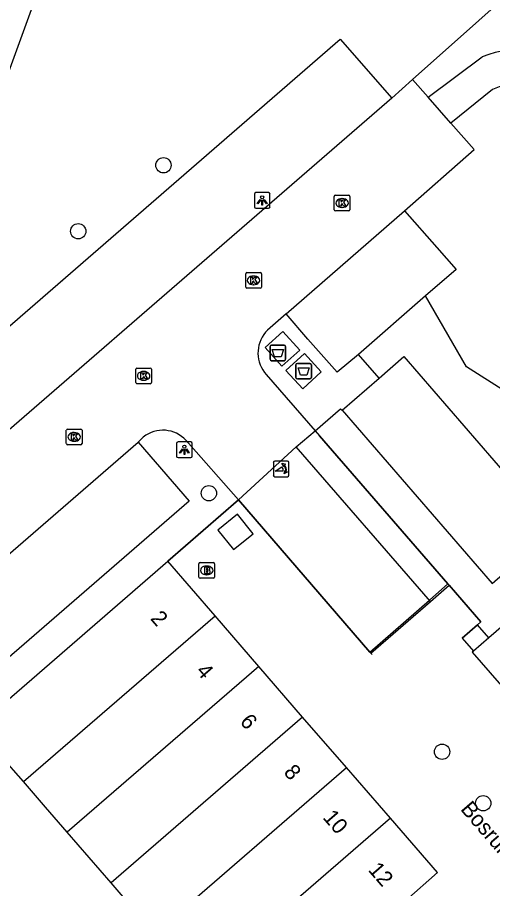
# Model space of a CAD drawing. Extents: x 156664 to 157568, y 383571 to 384421.
# Drawn here: x 156895.5 to 156925.9, y 384254.3 to 384310 of the extents above; entities that cross this region are included whole.
import ezdxf

# ---------------------------------------------------------------- set-up
doc = ezdxf.new("R2010")
doc.units = 0
for name, color, linetype in [('IMGEO_Afval_apart_plaats', 7, 'Continuous'), ('IMGEO_Berm_open', 7, 'Continuous'), ('IMGEO_Boom', 7, 'Continuous'), ('IMGEO_Brandkraan', 7, 'Continuous'), ('IMGEO_Kolk', 7, 'Continuous'), ('IMGEO_Lichtpunt', 7, 'Continuous'), ('IMGEO_Lijnafwatering', 7, 'Continuous'), ('IMGEO_Loofbos', 7, 'Continuous'), ('IMGEO_Muur', 7, 'Continuous'), ('IMGEO_Openbare_ruimte_label', 7, 'Continuous'), ('IMGEO_Pand', 7, 'Continuous'), ('IMGEO_Pand_nummerreeks', 7, 'Continuous'), ('IMGEO_Parkeervlak_open', 7, 'Continuous'), ('IMGEO_Poller', 7, 'Continuous'), ('IMGEO_Rijbaan_lokaal_open', 7, 'Continuous'), ('IMGEO_Voetpad_gesloten', 7, 'Continuous'), ('IMGEO_Voetpad_halfverhard', 7, 'Continuous'), ('IMGEO_Voetpad_open', 7, 'Continuous')]:
    doc.layers.add(name, color=color, linetype=linetype)

msp = doc.modelspace()

# ---------------------------------------------------------------- linework, layer by layer
at = {"layer": 'IMGEO_Afval_apart_plaats'}
for p, q in [((156911.678, 384288.16), (156911.678, 384288.96)), ((156911.678, 384288.96), (156911.678, 384288.16)), ((156911.778, 384289.06), (156912.568, 384289.06)), ((156912.568, 384289.06), (156911.778, 384289.06)), ((156912.668, 384288.96), (156912.668, 384288.16)), ((156912.668, 384288.16), (156912.668, 384288.96)), ((156912.568, 384288.06), (156911.778, 384288.06)), ((156911.778, 384288.06), (156912.568, 384288.06)), ((156913.424, 384287.89), (156914.214, 384287.89)), ((156914.214, 384287.89), (156913.424, 384287.89)), ((156913.324, 384286.99), (156913.324, 384287.79)), ((156913.324, 384287.79), (156913.324, 384286.99)), ((156914.314, 384287.79), (156914.314, 384286.99)), ((156914.314, 384286.99), (156914.314, 384287.79)), ((156914.214, 384286.89), (156913.424, 384286.89)), ((156913.424, 384286.89), (156914.214, 384286.89))]:
    msp.add_line(p, q, dxfattribs=at)
for points in [[(156911.821, 384288.774), (156912.525, 384288.774), (156912.376, 384288.304), (156911.97, 384288.304), (156911.821, 384288.774)], [(156913.467, 384287.604), (156914.171, 384287.604), (156914.022, 384287.134), (156913.616, 384287.134), (156913.467, 384287.604)]]:
    msp.add_lwpolyline(points, dxfattribs=at)
for centre, start, end in [((156911.778, 384288.96), 90, 180), ((156911.778, 384288.96), 90, 180), ((156912.568, 384288.96), 0, 90), ((156912.568, 384288.96), 360, 90), ((156911.778, 384288.16), 180, 270), ((156911.778, 384288.16), 180, 270), ((156912.568, 384288.16), 270, 0), ((156912.568, 384288.16), 270, 0), ((156913.424, 384287.79), 90, 180), ((156913.424, 384287.79), 90, 180), ((156914.214, 384287.79), 0, 90), ((156914.214, 384287.79), 360, 90), ((156913.424, 384286.99), 180, 270), ((156913.424, 384286.99), 180, 270), ((156914.214, 384286.99), 270, 0), ((156914.214, 384286.99), 270, 0)]:
    msp.add_arc(centre, 0.1, start, end, dxfattribs=at)
at = {"layer": 'IMGEO_Berm_open'}
msp.add_lwpolyline([(156918.639, 384286.952), (156917.316, 384288.456)], dxfattribs=at)
at = {"layer": 'IMGEO_Boom'}
for centre in [(156904.869, 384300.549), (156899.424, 384296.331), (156907.767, 384279.588), (156922.662, 384263.067), (156925.29, 384259.773)]:
    msp.add_circle(centre, 0.489, dxfattribs=at)
at = {"layer": 'IMGEO_Brandkraan'}
for p, q in [((156907.134, 384274.229), (156907.134, 384275.081)), ((156907.209, 384275.155), (156908.061, 384275.155)), ((156908.135, 384275.081), (156908.135, 384274.229)), ((156907.622, 384274.935), (156907.647, 384274.935)), ((156908.061, 384274.155), (156907.209, 384274.155)), ((156907.645, 384274.375), (156907.62, 384274.375))]:
    msp.add_line(p, q, dxfattribs=at)
for points in [[(156907.134, 384274.229), (156907.134, 384275.081)], [(156907.209, 384275.155), (156908.061, 384275.155)], [(156908.135, 384275.081), (156908.135, 384274.229)], [(156907.482, 384274.855), (156907.482, 384274.455), (156907.695, 384274.455)], [(156907.713, 384274.855), (156907.482, 384274.855)], [(156907.661, 384274.774), (156907.607, 384274.774), (156907.607, 384274.698)], [(156907.607, 384274.698), (156907.66, 384274.698)], [(156907.669, 384274.622), (156907.607, 384274.622), (156907.607, 384274.541)], [(156907.607, 384274.541), (156907.669, 384274.541)], [(156908.061, 384274.155), (156907.209, 384274.155)]]:
    msp.add_lwpolyline(points, dxfattribs=at)
for centre, radius, start, end in [((156907.211, 384275.079), 0.0765, 91.552, 178.448), ((156907.211, 384275.079), 0.0765, 91.552, 178.448), ((156908.059, 384275.079), 0.0765, 1.552, 88.448), ((156908.059, 384275.079), 0.0765, 1.552, 88.448), ((156907.662, 384274.736), 0.0379, 267.8285, 90.9355), ((156907.67, 384274.581), 0.0404, 269.8759, 90.5077), ((156907.701, 384274.706), 0.251, 268.6676, 293.5347), ((156907.717, 384274.71), 0.145, 59.4692, 91.5367), ((156907.742, 384274.757), 0.0922, 285.5137, 58.1501), ((156907.747, 384274.565), 0.105, 301.3115, 78.989), ((156907.211, 384274.231), 0.0765, 181.552, 268.448), ((156907.211, 384274.231), 0.0765, 181.552, 268.448), ((156908.059, 384274.231), 0.0765, 271.552, 358.448), ((156908.059, 384274.231), 0.0765, 271.552, 358.448)]:
    msp.add_arc(centre, radius, start, end, dxfattribs=at)
for centre, major_axis, ratio, start_param, end_param in [((156907.621, 384274.655), (-0.387, 0.002), 0.722429, 4.712389, 7.853982), ((156907.646, 384274.655), (-0.39, 0.002), 0.717154, 1.570796, 4.712389)]:
    msp.add_ellipse(centre, major_axis=major_axis, ratio=ratio, start_param=start_param, end_param=end_param, dxfattribs=at)
at = {"layer": 'IMGEO_Kolk'}
for p, q in [((156915.779, 384297.71), (156915.779, 384298.562)), ((156915.854, 384298.636), (156916.706, 384298.636)), ((156916.267, 384298.416), (156916.292, 384298.416)), ((156916.78, 384298.562), (156916.78, 384297.71)), ((156916.29, 384297.856), (156916.265, 384297.856)), ((156916.706, 384297.636), (156915.854, 384297.636)), ((156910.12, 384292.767), (156910.12, 384293.619)), ((156910.195, 384293.693), (156911.047, 384293.693)), ((156910.608, 384293.473), (156910.633, 384293.473)), ((156911.121, 384293.619), (156911.121, 384292.767)), ((156910.631, 384292.913), (156910.606, 384292.913)), ((156911.047, 384292.693), (156910.195, 384292.693)), ((156903.101, 384286.665), (156903.101, 384287.517)), ((156903.176, 384287.591), (156904.028, 384287.591)), ((156903.589, 384287.371), (156903.614, 384287.371)), ((156904.102, 384287.517), (156904.102, 384286.665)), ((156903.612, 384286.811), (156903.587, 384286.811)), ((156904.028, 384286.591), (156903.176, 384286.591)), ((156898.665, 384282.764), (156898.665, 384283.616)), ((156898.74, 384283.69), (156899.592, 384283.69)), ((156899.153, 384283.47), (156899.178, 384283.47)), ((156899.666, 384283.616), (156899.666, 384282.764)), ((156899.176, 384282.91), (156899.151, 384282.91)), ((156899.592, 384282.69), (156898.74, 384282.69))]:
    msp.add_line(p, q, dxfattribs=at)
for points in [[(156915.779, 384297.71), (156915.779, 384298.562)], [(156915.854, 384298.636), (156916.706, 384298.636)], [(156916.78, 384298.562), (156916.78, 384297.71)], [(156916.1, 384298.336), (156916.223, 384298.336), (156916.223, 384298.185), (156916.353, 384298.336), (156916.517, 384298.336), (156916.371, 384298.185), (156916.524, 384297.936), (156916.372, 384297.936), (156916.287, 384298.1), (156916.223, 384298.033), (156916.223, 384297.936), (156916.1, 384297.936), (156916.1, 384298.336)], [(156916.706, 384297.636), (156915.854, 384297.636)], [(156910.12, 384292.767), (156910.12, 384293.619)], [(156910.195, 384293.693), (156911.047, 384293.693)], [(156910.441, 384293.393), (156910.564, 384293.393), (156910.564, 384293.242), (156910.694, 384293.393), (156910.858, 384293.393), (156910.712, 384293.242), (156910.865, 384292.993), (156910.713, 384292.993), (156910.628, 384293.157), (156910.564, 384293.09), (156910.564, 384292.993), (156910.441, 384292.993), (156910.441, 384293.393)], [(156911.121, 384293.619), (156911.121, 384292.767)], [(156911.047, 384292.693), (156910.195, 384292.693)], [(156903.101, 384286.665), (156903.101, 384287.517)], [(156903.176, 384287.591), (156904.028, 384287.591)], [(156903.422, 384287.291), (156903.545, 384287.291), (156903.545, 384287.14), (156903.675, 384287.291), (156903.839, 384287.291), (156903.693, 384287.14), (156903.846, 384286.891), (156903.694, 384286.891), (156903.609, 384287.055), (156903.545, 384286.988), (156903.545, 384286.891), (156903.422, 384286.891), (156903.422, 384287.291)], [(156904.102, 384287.517), (156904.102, 384286.665)], [(156904.028, 384286.591), (156903.176, 384286.591)], [(156898.665, 384282.764), (156898.665, 384283.616)], [(156898.74, 384283.69), (156899.592, 384283.69)], [(156898.986, 384283.39), (156899.109, 384283.39), (156899.109, 384283.239), (156899.239, 384283.39), (156899.403, 384283.39), (156899.257, 384283.239), (156899.41, 384282.99), (156899.258, 384282.99), (156899.173, 384283.154), (156899.109, 384283.087), (156899.109, 384282.99), (156898.986, 384282.99), (156898.986, 384283.39)], [(156899.666, 384283.616), (156899.666, 384282.764)], [(156899.592, 384282.69), (156898.74, 384282.69)]]:
    msp.add_lwpolyline(points, dxfattribs=at)
for centre, start, end in [((156915.856, 384298.56), 91.552, 178.448), ((156915.856, 384298.56), 91.552, 178.448), ((156916.704, 384298.56), 1.552, 88.448), ((156916.704, 384298.56), 1.552, 88.448), ((156915.856, 384297.712), 181.552, 268.448), ((156915.856, 384297.712), 181.552, 268.448), ((156916.704, 384297.712), 271.552, 358.448), ((156916.704, 384297.712), 271.552, 358.448), ((156910.197, 384293.617), 91.552, 178.448), ((156910.197, 384293.617), 91.552, 178.448), ((156911.045, 384293.617), 1.552, 88.448), ((156911.045, 384293.617), 1.552, 88.448), ((156910.197, 384292.769), 181.552, 268.448), ((156910.197, 384292.769), 181.552, 268.448), ((156911.045, 384292.769), 271.552, 358.448), ((156911.045, 384292.769), 271.552, 358.448), ((156903.178, 384287.515), 91.552, 178.448), ((156903.178, 384287.515), 91.552, 178.448), ((156904.026, 384287.515), 1.552, 88.448), ((156904.026, 384287.515), 1.552, 88.448), ((156903.178, 384286.667), 181.552, 268.448), ((156903.178, 384286.667), 181.552, 268.448), ((156904.026, 384286.667), 271.552, 358.448), ((156904.026, 384286.667), 271.552, 358.448), ((156898.742, 384283.614), 91.552, 178.448), ((156898.742, 384283.614), 91.552, 178.448), ((156899.59, 384283.614), 1.552, 88.448), ((156899.59, 384283.614), 1.552, 88.448), ((156898.742, 384282.766), 181.552, 268.448), ((156898.742, 384282.766), 181.552, 268.448), ((156899.59, 384282.766), 271.552, 358.448), ((156899.59, 384282.766), 271.552, 358.448)]:
    msp.add_arc(centre, 0.0765, start, end, dxfattribs=at)
for centre, major_axis, ratio, start_param, end_param in [((156916.266, 384298.136), (-0.387, 0.002), 0.722429, 4.712389, 7.853982), ((156916.291, 384298.136), (-0.39, 0.002), 0.717154, 1.570796, 4.712389), ((156910.607, 384293.193), (-0.387, 0.002), 0.722429, 4.712389, 7.853982), ((156910.632, 384293.193), (-0.39, 0.002), 0.717154, 1.570796, 4.712389), ((156903.588, 384287.091), (-0.387, 0.002), 0.722429, 4.712389, 7.853982), ((156903.613, 384287.091), (-0.39, 0.002), 0.717154, 1.570796, 4.712389), ((156899.152, 384283.19), (-0.387, 0.002), 0.722429, 4.712389, 7.853982), ((156899.177, 384283.19), (-0.39, 0.002), 0.717154, 1.570796, 4.712389)]:
    msp.add_ellipse(centre, major_axis=major_axis, ratio=ratio, start_param=start_param, end_param=end_param, dxfattribs=at)
at = {"layer": 'IMGEO_Lichtpunt'}
for p, q in [((156910.677, 384298.708), (156910.677, 384297.901)), ((156910.677, 384298.708), (156910.677, 384297.901)), ((156911.579, 384298.803), (156910.771, 384298.803)), ((156911.579, 384298.803), (156910.771, 384298.803)), ((156911.673, 384297.901), (156911.673, 384298.708)), ((156911.673, 384297.901), (156911.673, 384298.708)), ((156910.771, 384297.807), (156911.579, 384297.807)), ((156910.771, 384297.807), (156911.579, 384297.807)), ((156906.608, 384282.865), (156905.8, 384282.865)), ((156906.608, 384282.865), (156905.8, 384282.865)), ((156905.706, 384282.77), (156905.706, 384281.963)), ((156905.706, 384282.77), (156905.706, 384281.963)), ((156906.702, 384281.963), (156906.702, 384282.77)), ((156906.702, 384281.963), (156906.702, 384282.77)), ((156905.8, 384281.869), (156906.608, 384281.869)), ((156905.8, 384281.869), (156906.608, 384281.869))]:
    msp.add_line(p, q, dxfattribs=at)
for points in [[(156911.051, 384298.372), (156911.09, 384298.344), (156910.902, 384298.082), (156910.864, 384298.109), (156911.051, 384298.372)], [(156911.153, 384298.324), (156911.2, 384298.324), (156911.2, 384298.002), (156911.153, 384298.002), (156911.153, 384298.324)], [(156911.263, 384298.344), (156911.301, 384298.371), (156911.488, 384298.109), (156911.449, 384298.081), (156911.263, 384298.344)], [(156906.08, 384282.434), (156906.119, 384282.406), (156905.931, 384282.144), (156905.893, 384282.171), (156906.08, 384282.434)], [(156906.182, 384282.386), (156906.229, 384282.386), (156906.229, 384282.064), (156906.182, 384282.064), (156906.182, 384282.386)], [(156906.292, 384282.406), (156906.33, 384282.433), (156906.517, 384282.171), (156906.478, 384282.143), (156906.292, 384282.406)]]:
    msp.add_lwpolyline(points, dxfattribs=at)
for centre in [(156911.176, 384298.506), (156906.205, 384282.568)]:
    msp.add_circle(centre, 0.0994, dxfattribs=at)
for centre, start, end in [((156910.771, 384298.708), 90, 180), ((156910.771, 384298.708), 90, 180), ((156911.579, 384298.708), 0, 90), ((156911.579, 384298.708), 0, 90), ((156910.771, 384297.901), 180, 270), ((156910.771, 384297.901), 180, 270), ((156911.579, 384297.901), 270, 0), ((156911.579, 384297.901), 270, 360), ((156905.8, 384282.77), 90, 180), ((156905.8, 384282.77), 90, 180), ((156906.608, 384282.77), 0, 90), ((156906.608, 384282.77), 0, 90), ((156905.8, 384281.963), 180, 270), ((156905.8, 384281.963), 180, 270), ((156906.608, 384281.963), 270, 0), ((156906.608, 384281.963), 270, 360)]:
    msp.add_arc(centre, 0.0946, start, end, dxfattribs=at)
at = {"layer": 'IMGEO_Lijnafwatering'}
msp.add_lwpolyline([(156918.044, 384269.439), (156921.85, 384272.758), (156923.04, 384273.795)], dxfattribs=at)
at = {"layer": 'IMGEO_Loofbos'}
for points in [[(156920.779, 384306.033), (156933.486, 384317.366)], [(156946.464, 384285.343), (156940.187, 384279.465), (156934.032, 384281.434), (156924.213, 384287.669), (156921.611, 384292.197)]]:
    msp.add_lwpolyline(points, dxfattribs=at)
at = {"layer": 'IMGEO_Muur'}
for points in [[(156923.04, 384273.795), (156914.83, 384283.252)], [(156909.656, 384279.17), (156905.142, 384275.238)], [(156918.044, 384269.439), (156909.656, 384279.17)], [(156923.11, 384273.714), (156923.04, 384273.795)], [(156924.923, 384271.172), (156925.147, 384271.369), (156923.11, 384273.714)], [(156923.948, 384270.32), (156924.923, 384271.172)], [(156918.114, 384269.357), (156918.044, 384269.439)], [(156918.189, 384269.271), (156918.114, 384269.357)]]:
    msp.add_lwpolyline(points, dxfattribs=at)
at = {"layer": 'IMGEO_Pand'}
for points in [[(156902.064, 384326.017), (156889.74, 384292.159), (156855.895, 384304.479), (156868.199, 384338.324), (156902.064, 384326.017)], [(156895.921, 384261.156), (156894.513, 384262.782), (156892.903, 384264.64), (156905.142, 384275.238)], [(156908.162, 384271.749), (156905.142, 384275.238)], [(156931.448, 384275.362), (156925.642, 384270.338)], [(156895.921, 384261.156), (156908.162, 384271.749)], [(156910.96, 384268.517), (156908.162, 384271.749)], [(156925.642, 384270.338), (156924.671, 384269.498)], [(156924.671, 384269.498), (156924.595, 384269.432), (156927.603, 384265.957)], [(156910.96, 384268.517), (156898.723, 384257.922)], [(156913.757, 384265.285), (156910.96, 384268.517)], [(156913.757, 384265.285), (156901.526, 384254.688)], [(156916.555, 384262.053), (156913.757, 384265.285)], [(156904.328, 384251.453), (156916.555, 384262.053)], [(156919.359, 384258.813), (156916.555, 384262.053)], [(156898.723, 384257.922), (156897.327, 384259.534), (156895.921, 384261.156)], [(156919.359, 384258.813), (156907.137, 384248.212)], [(156920.35, 384253.561), (156922.366, 384255.339), (156919.359, 384258.813)], [(156901.526, 384254.688), (156900.121, 384256.309), (156898.723, 384257.922)], [(156904.328, 384251.453), (156902.944, 384253.05), (156901.526, 384254.688)]]:
    msp.add_lwpolyline(points, dxfattribs=at)
at = {"layer": 'IMGEO_Parkeervlak_open'}
for points in [[(156881.088, 384277.119), (156880.566, 384277.726), (156916.164, 384308.614), (156919.449, 384304.847)], [(156920.266, 384297.637), (156922.327, 384295.29), (156923.556, 384293.891), (156921.611, 384292.197)], [(156921.611, 384292.197), (156917.316, 384288.456)], [(156917.316, 384288.456), (156915.965, 384287.32), (156914.093, 384289.439), (156912.712, 384291.056)], [(156903.248, 384282.862), (156906.505, 384279.09), (156884.305, 384259.85), (156881.05, 384263.616)]]:
    msp.add_lwpolyline(points, dxfattribs=at)
at = {"layer": 'IMGEO_Poller'}
for p, q in [((156911.886, 384281.546), (156911.886, 384280.739)), ((156911.886, 384281.546), (156911.886, 384280.739)), ((156912.788, 384281.641), (156911.98, 384281.641)), ((156912.788, 384281.641), (156911.98, 384281.641)), ((156912.882, 384280.739), (156912.882, 384281.546)), ((156912.882, 384280.739), (156912.882, 384281.546)), ((156911.98, 384280.644), (156912.788, 384280.644)), ((156911.98, 384280.644), (156912.788, 384280.644))]:
    msp.add_line(p, q, dxfattribs=at)
for points in [[(156912.521, 384280.997), (156912.008, 384280.997), (156912.438, 384281.272)], [(156912.565, 384281.37), (156912.553, 384281.297), (156912.428, 384281.502)], [(156912.428, 384281.502), (156912.659, 384281.436), (156912.588, 384281.404)], [(156912.581, 384280.825), (156912.647, 384281.056), (156912.677, 384280.988)], [(156912.713, 384280.961), (156912.785, 384280.95), (156912.581, 384280.825)]]:
    msp.add_lwpolyline(points, dxfattribs=at)
for centre, radius, start, end in [((156911.98, 384281.546), 0.0946, 90, 180), ((156911.98, 384281.546), 0.0946, 90, 180), ((156912.193, 384281.047), 0.332, 351.3247, 42.4854), ((156912.207, 384281.057), 0.476, 351.7527, 41.1691), ((156912.207, 384281.057), 0.516, 349.3569, 42.2912), ((156912.788, 384281.546), 0.0946, 0, 90), ((156912.788, 384281.546), 0.0946, 0, 90), ((156911.98, 384280.739), 0.0946, 180, 270), ((156911.98, 384280.739), 0.0946, 180, 270), ((156912.788, 384280.739), 0.0946, 270, 0), ((156912.788, 384280.739), 0.0946, 270, 0)]:
    msp.add_arc(centre, radius, start, end, dxfattribs=at)
at = {"layer": 'IMGEO_Rijbaan_lokaal_open'}
for points in [[(156919.449, 384304.847), (156920.779, 384306.033)], [(156921.768, 384304.903), (156920.779, 384306.033)], [(156919.449, 384304.847), (156883.807, 384273.954)], [(156923.23, 384303.234), (156921.768, 384304.903)], [(156920.266, 384297.637), (156924.705, 384301.55), (156923.23, 384303.234)], [(156912.712, 384291.056), (156920.266, 384297.637)], [(156912.712, 384291.056), (156911.517, 384290.014)], [(156911.321, 384287.31), (156911.436, 384287.174), (156914.55, 384283.577)], [(156913.341, 384282.548), (156914.55, 384283.577)], [(156881.05, 384263.616), (156903.248, 384282.862)], [(156903.581, 384283.18), (156903.248, 384282.862)], [(156909.656, 384279.17), (156906.319, 384282.966)], [(156909.656, 384279.17), (156913.341, 384282.548)]]:
    msp.add_lwpolyline(points, dxfattribs=at)
for centre, radius, start, end in [((156912.964, 384288.55), 2.058, 134.6668, 217.0415), ((156904.835, 384281.596), 2.02, 42.6948, 128.3669)]:
    msp.add_arc(centre, radius, start, end, dxfattribs=at)
at = {"layer": 'IMGEO_Voetpad_gesloten'}
for points in [[(156912.438, 384287.717), (156913.587, 384288.738), (156912.49, 384289.934), (156911.358, 384288.902), (156912.438, 384287.717)], [(156913.764, 384286.264), (156912.693, 384287.438), (156913.874, 384288.516), (156914.945, 384287.342), (156913.764, 384286.264)], [(156918.639, 384286.952), (156920.225, 384288.334), (156929.811, 384277.257)], [(156916.278, 384284.895), (156918.639, 384286.952)], [(156916.278, 384284.895), (156925.856, 384273.817), (156929.811, 384277.257)]]:
    msp.add_lwpolyline(points, dxfattribs=at)
at = {"layer": 'IMGEO_Voetpad_halfverhard'}
for points in [[(156921.768, 384304.903), (156925.223, 384307.475)], [(156925.888, 384305.399), (156923.23, 384303.234)], [(156905.142, 384275.238), (156909.656, 384279.17)], [(156910.604, 384276.99), (156909.595, 384278.248), (156908.335, 384277.22), (156909.343, 384275.982), (156910.604, 384276.99)], [(156924.923, 384271.172), (156923.948, 384270.32), (156924.671, 384269.498)]]:
    msp.add_lwpolyline(points, dxfattribs=at)
for centre, radius, start, end in [((156927.233, 384303.004), 4.902, 33.2943, 114.2061), ((156927.225, 384302.38), 3.302, 51.283, 113.8787)]:
    msp.add_arc(centre, radius, start, end, dxfattribs=at)
at = {"layer": 'IMGEO_Voetpad_open'}
for points in [[(156914.55, 384283.577), (156916.18, 384284.984), (156916.278, 384284.895)], [(156914.55, 384283.577), (156914.83, 384283.252), (156923.04, 384273.795), (156923.11, 384273.714)], [(156921.921, 384272.677), (156913.341, 384282.548)], [(156909.656, 384279.17), (156918.044, 384269.439), (156918.114, 384269.357), (156921.921, 384272.677)], [(156921.921, 384272.677), (156923.11, 384273.714)], [(156923.11, 384273.714), (156925.147, 384271.369), (156924.923, 384271.172)], [(156925.642, 384270.338), (156924.923, 384271.172)]]:
    msp.add_lwpolyline(points, dxfattribs=at)

# ---------------------------------------------------------------- texts
at = {"layer": 'IMGEO_Openbare_ruimte_label'}
msp.add_text('Bosruiter', height=1, rotation=310.8624, dxfattribs=at).set_placement((156923.795, 384259.374))
at = {"layer": 'IMGEO_Pand_nummerreeks'}
for s, p in [('2', (156903.99, 384271.557)), ('4', (156906.903, 384268.192)), ('6', (156909.701, 384264.96)), ('8', (156912.5, 384261.725)), ('10', (156915, 384258.838)), ('12', (156917.899, 384255.488))]:
    msp.add_text(s, height=1, rotation=310.8797, dxfattribs=at).set_placement(p)

doc.saveas('drawing.dxf')
